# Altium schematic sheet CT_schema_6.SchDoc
size 277 x 170 mm
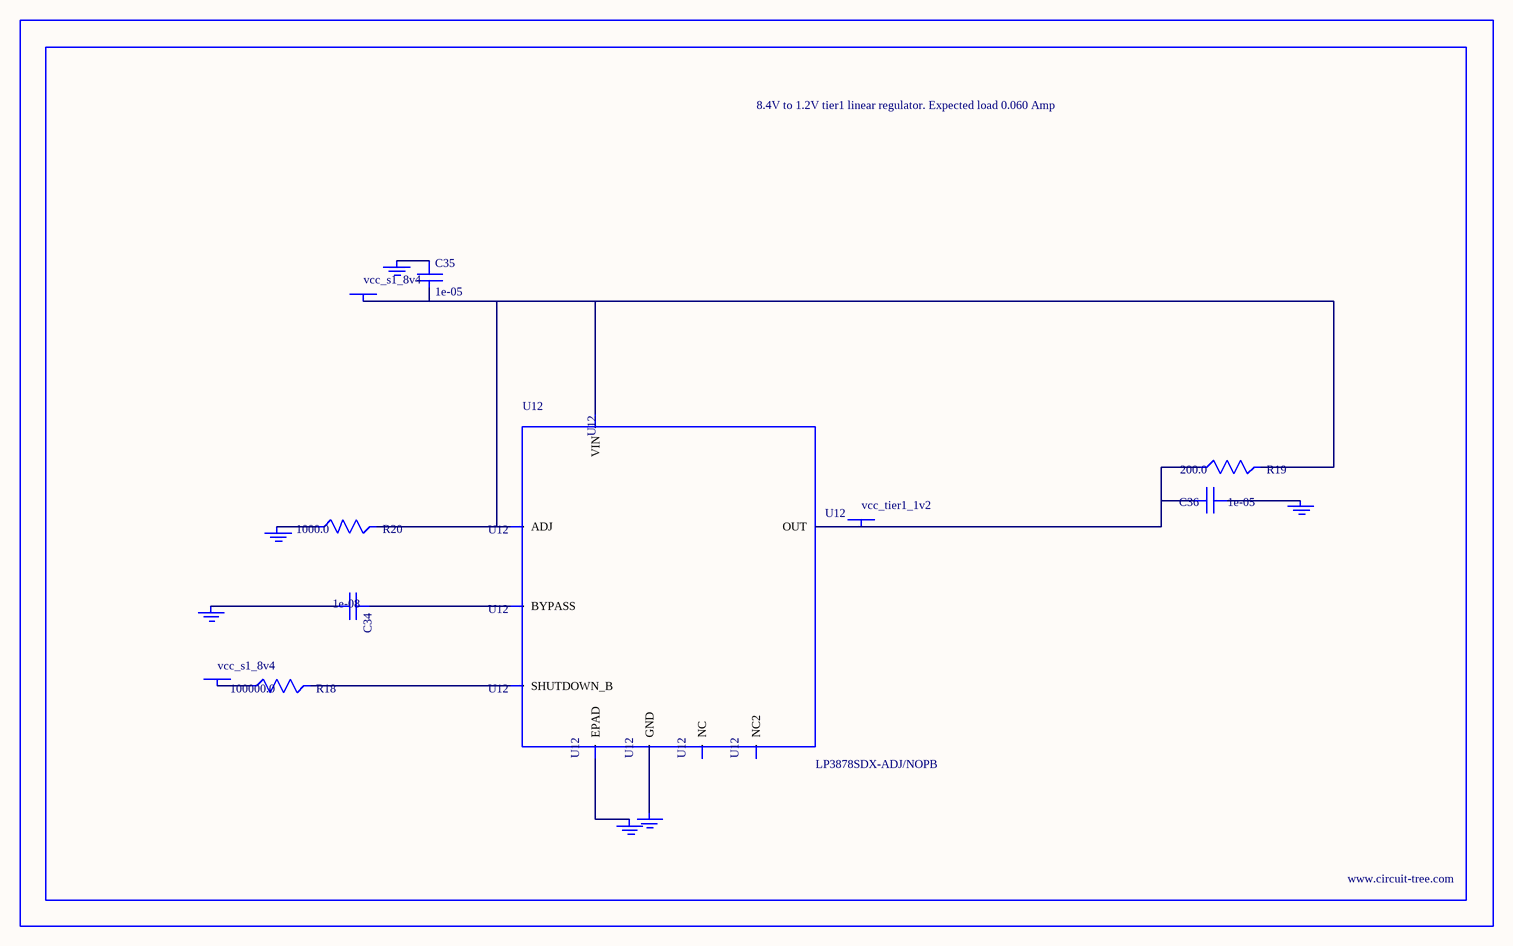
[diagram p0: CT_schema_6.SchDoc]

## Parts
BORDER5  (no value)
C34  1e-08  [C0402]
C35  1e-05  [C1206]
C36  1e-05  [C0805]
GND_INSTANCE_5_0  (no value)
GND_INSTANCE_5_1  (no value)
GND_INSTANCE_5_2  (no value)
GND_INSTANCE_5_3  (no value)
GND_INSTANCE_5_4  (no value)
GND_INSTANCE_5_5  (no value)
POWER_INSTANCE_5_0  vcc_s1_8v4
POWER_INSTANCE_5_1  vcc_s1_8v4
POWER_INSTANCE_5_2  vcc_tier1_1v2
R18  100000.0  [R0603]
R19  200.0  [R0603]
R20  1000.0  [R0603]
U12  LP3878SDX-ADJ/NOPB  [WSON-8]

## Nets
NetC34_1: C34.1 U12.1(BYPASS)
NetC34_2: C34.2 GND_INSTANCE_5_0.0(GND)
NetC35_1: C35.1 GND_INSTANCE_5_1.0(GND)
NetC35_2: C35.2 POWER_INSTANCE_5_0.0(PWR) R19.2 R20.2 U12.4(VIN) U12.6(ADJ)
NetC36_1: C36.1 GND_INSTANCE_5_2.0(GND)
NetC36_2: C36.2 POWER_INSTANCE_5_2.0(PWR) R19.1 U12.5(OUT)
NetGND_INSTANCE_5_3_0: GND_INSTANCE_5_3.0(GND) R20.1
NetGND_INSTANCE_5_4_0: GND_INSTANCE_5_4.0(GND) U12.PAD(EPAD)
NetGND_INSTANCE_5_5_0: GND_INSTANCE_5_5.0(GND) U12.3(GND)
NetPOWER_INSTANCE_5_1_0: POWER_INSTANCE_5_1.0(PWR) R18.1
NetR18_2: R18.2 U12.8(SHUTDOWN_B)

Not connected (* = marked no-connect by the designer): U12 2(NC) 7(NC2)

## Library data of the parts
BORDER5 = BORDER_PAGE5
C34 = C0402C103K3RAC
C35 = C1206C106K3RACTU
C36 = GRM219R60J106ME19D
GND_INSTANCE_5_0-GND_INSTANCE_5_5 = GND
POWER_INSTANCE_5_0-POWER_INSTANCE_5_2 = PWR
R18 = RC0603JR-07100KL
R19 = RC0603JR-07200RL
R20 = RC0603JR-071KL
